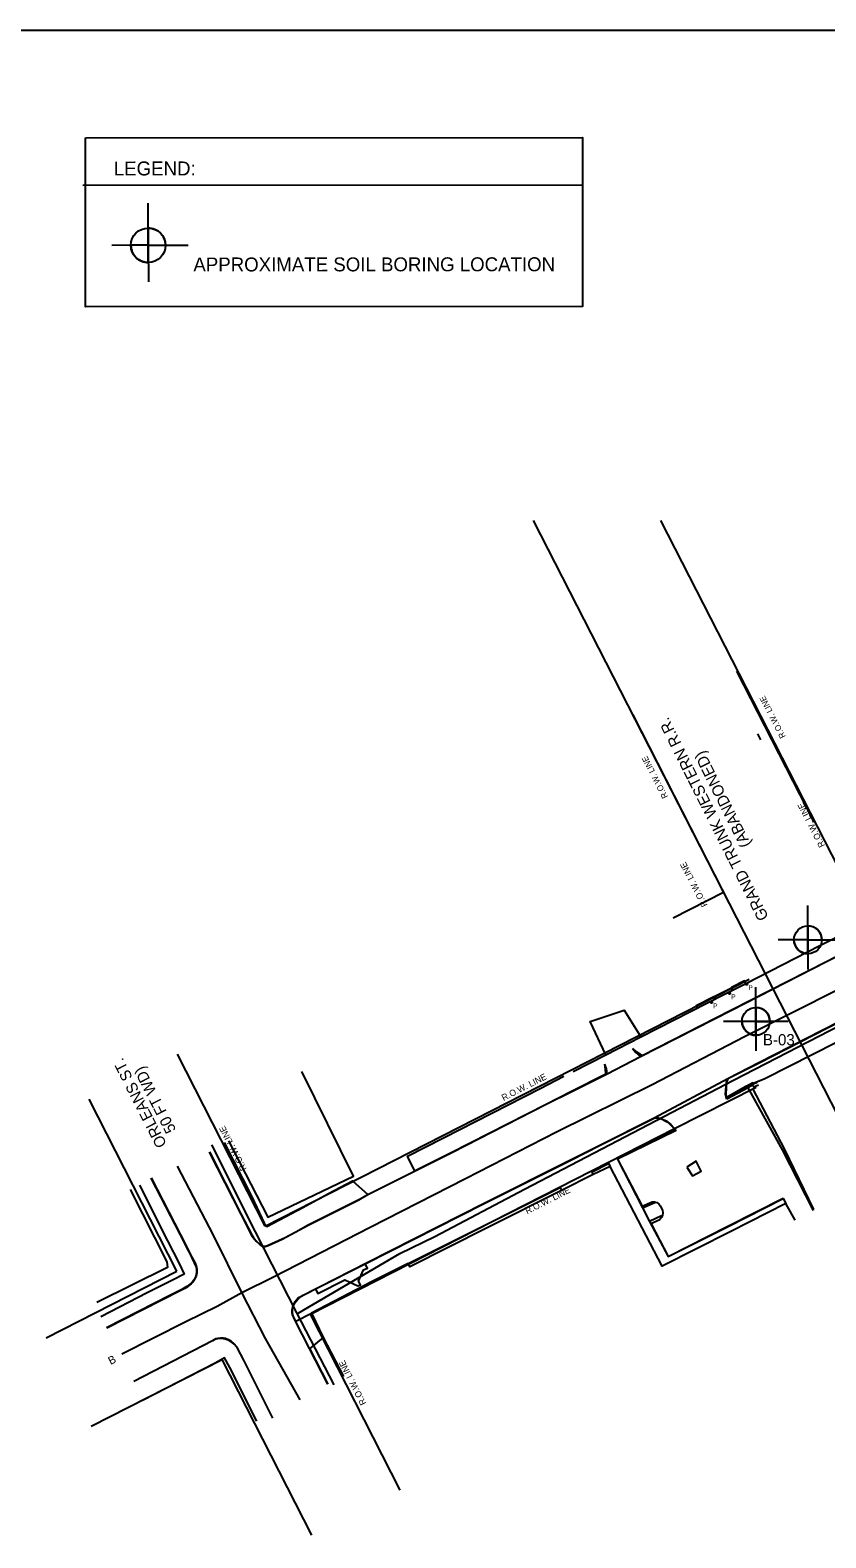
# Model space of a CAD drawing. Extents: x 19007.1 to 19038.2, y 21497.8 to 21516.9.
# Drawn here: x 19024.08 to 19030.07, y 21505.55 to 21516.9 of the extents above; entities that cross this region are included whole.
import ezdxf

# ---------------------------------------------------------------- set-up
doc = ezdxf.new("R2010")
doc.units = 0
for name, color, linetype in [('BORDER', 7, 'Continuous'), ('DETAIL_TEXT_DIMEN_PR', 7, 'Continuous'), ('G-ANNO-TTLB', 7, 'Continuous'), ('TYPICAL_TEXT_DIMEN_PR', 7, 'Continuous'), ('V-ANNO-TEXT', 7, 'Continuous'), ('V-BLDG-OTLN', 7, 'Continuous'), ('V-DEMO-PVMT', 7, 'Continuous'), ('V-PROP-RWAY', 7, 'Continuous'), ('V-PROP-RWAY-IDEN', 7, 'Continuous'), ('V-PVMT-CNTR', 7, 'Continuous'), ('V-PVMT-ROAD', 7, 'Continuous'), ('V-SITE-FEAT-DEMO', 7, 'Continuous'), ('V-SITE-FENC', 7, 'Continuous'), ('V-SITE-STRS', 7, 'Continuous'), ('V-SITE-WALK', 7, 'Continuous'), ('V-UTIL-OVHD', 7, 'Continuous')]:
    doc.layers.add(name, color=color, linetype=linetype)

msp = doc.modelspace()

# ---------------------------------------------------------------- linework, layer by layer
at = {"layer": 'G-ANNO-TTLB'}
msp.add_lwpolyline([(19036.479, 21497.785), (19007.136, 21497.785), (19007.136, 21516.9), (19036.479, 21516.9)], close=True, dxfattribs=at)
at = {"layer": 'TYPICAL_TEXT_DIMEN_PR'}
for p, q in [((19024.473, 21515.732), (19028.235, 21515.735)), ((19024.966, 21515.28), (19024.966, 21515.598)), ((19024.966, 21515.28), (19024.691, 21515.279)), ((19024.966, 21515.28), (19024.967, 21515.004)), ((19024.966, 21515.28), (19025.267, 21515.28)), ((19029.931, 21510.05), (19029.93, 21510.308)), ((19029.931, 21510.05), (19029.707, 21510.05)), ((19029.931, 21510.05), (19029.931, 21509.827)), ((19029.931, 21510.05), (19030.174, 21510.05)), ((19029.54, 21509.436), (19029.539, 21509.694)), ((19029.54, 21509.436), (19029.296, 21509.436)), ((19029.54, 21509.436), (19029.54, 21509.213)), ((19029.783, 21509.436), (19029.54, 21509.436))]:
    msp.add_line(p, q, dxfattribs=at)
msp.add_lwpolyline([(19024.493, 21516.09), (19028.234, 21516.093), (19028.235, 21514.819), (19024.494, 21514.817)], close=True, dxfattribs=at)
for points in [[(19024.966, 21515.41), (19024.966, 21515.28), (19025.096, 21515.28)], [(19024.966, 21515.15), (19024.966, 21515.28), (19024.836, 21515.28)], [(19029.93, 21510.155), (19029.931, 21510.05), (19030.036, 21510.05)], [(19029.931, 21509.945), (19029.931, 21510.05), (19029.825, 21510.05)], [(19029.539, 21509.542), (19029.54, 21509.436), (19029.645, 21509.436)], [(19029.54, 21509.331), (19029.54, 21509.436), (19029.434, 21509.436)]]:
    msp.add_lwpolyline(points, dxfattribs=at)
for centre, radius in [((19024.966, 21515.28), 0.13), ((19029.931, 21510.05), 0.105), ((19029.54, 21509.436), 0.105)]:
    msp.add_circle(centre, radius, dxfattribs=at)
for centre, radius, start, end in [((19024.966, 21515.28), 0.13, 0.0399, 90.0399), ((19024.966, 21515.28), 0.13, 180.0399, 270.0399), ((19029.931, 21510.05), 0.105, 0.0399, 90.0399), ((19029.931, 21510.05), 0.105, 180.0399, 270.0399), ((19029.54, 21509.436), 0.105, 0.0399, 90.0399), ((19029.54, 21509.436), 0.105, 180.0399, 270.0399)]:
    msp.add_arc(centre, radius, start, end, dxfattribs=at)
at = {"layer": 'V-BLDG-OTLN'}
for points in [[(19029.361, 21509.674), (19029.355, 21509.685), (19029.225, 21509.62), (19029.232, 21509.607)], [(19029.465, 21509.721), (19029.455, 21509.741), (19029.357, 21509.69), (19029.365, 21509.674)], [(19029.229, 21509.606), (19029.222, 21509.621), (19029.091, 21509.553), (19029.098, 21509.539)], [(19029.55, 21508.975), (19029.522, 21508.963), (19029.516, 21508.973), (19029.466, 21508.946), (19029.471, 21508.934), (19029.515, 21508.957), (19029.524, 21508.942), (19029.559, 21508.959)], [(19029.836, 21507.94), (19029.766, 21508.065), (19029.35, 21507.854), (19028.833, 21507.592), (19028.442, 21508.344), (19028.316, 21508.282), (19028.076, 21508.161), (19027.518, 21507.882), (19026.936, 21507.588), (19026.923, 21507.612), (19026.646, 21507.474), (19026.194, 21507.238), (19026.283, 21507.056), (19026.435, 21506.761)], [(19028.316, 21508.282), (19028.307, 21508.304), (19028.431, 21508.365), (19028.442, 21508.344)], [(19026.923, 21507.612), (19027.505, 21507.903), (19028.067, 21508.185), (19028.076, 21508.161)], [(19025.784, 21506.424), (19025.58, 21506.829), (19025.539, 21506.902), (19025.469, 21506.862), (19024.923, 21506.582)]]:
    msp.add_lwpolyline(points, dxfattribs=at)
at = {"layer": 'V-DEMO-PVMT'}
for points in [[(19028.154, 21508.908), (19028.419, 21509.041), (19028.546, 21509.107), (19028.672, 21509.171), (19029.356, 21509.521), (19030.072, 21509.886), (19030.709, 21510.21), (19030.76, 21510.239), (19031.052, 21510.392)], [(19028.164, 21509.058), (19028.409, 21509.183), (19028.674, 21509.32), (19029.298, 21509.638), (19029.465, 21509.721), (19030.021, 21510.007), (19030.58, 21510.287), (19030.524, 21510.391)], [(19028.612, 21509.233), (19028.641, 21509.206), (19028.684, 21509.18), (19029.355, 21509.523), (19030.071, 21509.887), (19030.646, 21510.185), (19030.683, 21510.202)], [(19028.361, 21508.502), (19028.774, 21508.709), (19029.328, 21509.006), (19029.561, 21509.125), (19030.285, 21509.494), (19030.794, 21509.753), (19030.943, 21509.826), (19031.258, 21509.988)], [(19029.318, 21508.865), (19029.315, 21508.887), (19029.321, 21508.977), (19029.333, 21509.007), (19029.563, 21509.123), (19030.284, 21509.492), (19030.796, 21509.751), (19030.944, 21509.823)], [(19028.61, 21509.232), (19028.635, 21509.201), (19028.672, 21509.171)], [(19028.153, 21508.91), (19028.41, 21509.04), (19028.407, 21509.077), (19028.403, 21509.113)], [(19028.419, 21509.041), (19028.414, 21509.078), (19028.403, 21509.113)], [(19029.322, 21508.85), (19029.311, 21508.887), (19029.319, 21508.976), (19029.328, 21509.006)], [(19028.362, 21508.5), (19028.774, 21508.706), (19028.781, 21508.709), (19028.794, 21508.71), (19028.807, 21508.709), (19028.834, 21508.699), (19028.869, 21508.68), (19028.884, 21508.669), (19028.908, 21508.646), (19028.919, 21508.634), (19028.925, 21508.627)], [(19028.774, 21508.709), (19028.802, 21508.708), (19028.815, 21508.706), (19028.835, 21508.7), (19028.853, 21508.692), (19028.864, 21508.686), (19028.886, 21508.67), (19028.899, 21508.659), (19028.921, 21508.635), (19028.939, 21508.613)], [(19028.925, 21508.627), (19028.935, 21508.614)]]:
    msp.add_lwpolyline(points, dxfattribs=at)
at = {"layer": 'V-PROP-RWAY'}
for p, q in [((19031.526, 21506.047), (19027.866, 21513.207)), ((19028.821, 21513.208), (19032.481, 21506.048)), ((19029.394, 21512.072), (19029.976, 21510.937)), ((19028.613, 21511.743), (19029.296, 21510.407)), ((19029.552, 21511.6), (19029.575, 21511.556)), ((19029.296, 21510.407), (19028.918, 21510.213)), ((19025.847, 21507.894), (19029.489, 21509.753)), ((19025.847, 21507.894), (19025.187, 21509.188)), ((19028.927, 21508.628), (19029.542, 21508.941)), ((19025.182, 21507.555), (19024.522, 21508.849)), ((19026.187, 21507.23), (19028.927, 21508.628)), ((19024.197, 21507.053), (19025.182, 21507.555)), ((19026.862, 21505.905), (19026.187, 21507.23)), ((19024.536, 21506.388), (19025.522, 21506.89)), ((19026.197, 21505.566), (19025.522, 21506.89))]:
    msp.add_line(p, q, dxfattribs=at)
at = {"layer": 'V-PVMT-CNTR'}
for points in [[(19024.768, 21506.931), (19025.248, 21507.176), (19025.486, 21507.292), (19025.671, 21507.393), (19025.91, 21507.513), (19026.637, 21507.887), (19027.353, 21508.253), (19028.04, 21508.603), (19028.758, 21508.961), (19029.453, 21509.321), (19030.166, 21509.682), (19030.805, 21510.009), (19031.46, 21510.342), (19032.157, 21510.701), (19032.83, 21511.045), (19033.573, 21511.424), (19034.313, 21511.797), (19035, 21512.147), (19035.429, 21512.364)], [(19026.11, 21506.586), (19025.85, 21507.047), (19025.671, 21507.393), (19025.457, 21507.825), (19025.187, 21508.346)]]:
    msp.add_lwpolyline(points, dxfattribs=at)
at = {"layer": 'V-PVMT-ROAD'}
for points in [[(19028.409, 21509.183), (19028.292, 21509.436), (19028.547, 21509.521), (19028.674, 21509.32)], [(19025.426, 21508.451), (19025.662, 21507.985), (19025.743, 21507.826), (19025.753, 21507.81), (19025.779, 21507.781), (19025.806, 21507.755), (19025.826, 21507.743), (19025.836, 21507.74), (19025.846, 21507.741), (19025.869, 21507.749), (19025.975, 21507.796), (19026.17, 21507.9), (19026.552, 21508.092), (19026.618, 21508.131), (19027.25, 21508.448), (19027.962, 21508.812), (19028.154, 21508.908)], [(19026.971, 21508.311), (19027.247, 21508.449), (19027.96, 21508.812), (19028.153, 21508.91)], [(19029.319, 21508.864), (19029.332, 21508.867), (19029.466, 21508.946)], [(19029.973, 21508.011), (19029.739, 21508.469), (19029.504, 21508.894), (19029.481, 21508.936), (19029.322, 21508.85)], [(19028.935, 21508.614), (19028.497, 21508.399), (19028.687, 21508.031), (19028.74, 21507.929), (19028.879, 21507.664), (19029.33, 21507.891), (19029.745, 21508.101), (19029.766, 21508.065)], [(19028.939, 21508.613), (19028.499, 21508.399), (19028.683, 21508.043), (19028.742, 21508.069), (19028.758, 21508.076), (19028.776, 21508.077), (19028.793, 21508.072), (19028.808, 21508.061), (19028.819, 21508.047), (19028.819, 21508.046), (19028.837, 21508.013), (19028.84, 21507.994), (19028.837, 21507.975), (19028.829, 21507.958), (19028.816, 21507.944), (19028.808, 21507.94), (19028.752, 21507.911), (19028.88, 21507.666), (19029.329, 21507.893), (19029.746, 21508.104)], [(19025.427, 21508.453), (19025.663, 21507.987), (19025.745, 21507.828), (19025.758, 21507.808), (19025.765, 21507.799), (19025.779, 21507.782), (19025.798, 21507.763), (19025.809, 21507.755), (19025.825, 21507.745), (19025.834, 21507.743), (19025.845, 21507.743), (19025.852, 21507.744), (19025.868, 21507.75), (19025.973, 21507.798), (19025.992, 21507.806), (19026.078, 21507.852), (19026.166, 21507.901), (19026.55, 21508.094)], [(19026.318, 21506.703), (19026.18, 21506.973), (19026.075, 21507.178), (19026.061, 21507.205), (19026.052, 21507.228), (19026.049, 21507.24), (19026.049, 21507.261), (19026.051, 21507.274), (19026.06, 21507.301), (19026.072, 21507.326), (19026.08, 21507.336), (19026.093, 21507.351), (19026.105, 21507.36), (19026.132, 21507.375), (19026.618, 21507.622), (19027.495, 21508.066), (19028.15, 21508.396), (19028.361, 21508.502)], [(19026.077, 21507.177), (19026.062, 21507.205), (19026.057, 21507.217), (19026.052, 21507.241), (19026.052, 21507.261), (19026.054, 21507.275), (19026.063, 21507.301), (19026.072, 21507.318), (19026.079, 21507.329), (19026.096, 21507.349), (19026.119, 21507.367), (19026.132, 21507.375), (19026.224, 21507.421), (19026.599, 21507.611), (19027.495, 21508.064), (19028.151, 21508.394), (19028.362, 21508.5)], [(19029.021, 21508.337), (19029.063, 21508.273), (19029.128, 21508.308), (19029.089, 21508.383), (19029.021, 21508.337)], [(19024.986, 21508.255), (19025.207, 21507.828), (19025.269, 21507.705), (19025.293, 21507.659), (19025.313, 21507.618), (19025.323, 21507.595), (19025.326, 21507.584), (19025.329, 21507.567), (19025.329, 21507.542), (19025.324, 21507.518), (19025.32, 21507.508), (19025.31, 21507.488), (19025.3, 21507.475), (19025.287, 21507.462), (19025.257, 21507.439), (19025.22, 21507.416), (19025.2, 21507.406), (19025.134, 21507.375), (19024.653, 21507.128)], [(19024.989, 21508.257), (19025.209, 21507.828), (19025.295, 21507.66), (19025.316, 21507.619), (19025.326, 21507.596), (19025.329, 21507.585), (19025.332, 21507.568), (19025.332, 21507.543), (19025.326, 21507.518), (19025.32, 21507.502), (19025.308, 21507.482), (19025.301, 21507.472), (19025.289, 21507.459), (19025.28, 21507.451), (19025.261, 21507.437), (19025.242, 21507.425), (19025.201, 21507.405), (19024.654, 21507.125)], [(19024.831, 21508.169), (19025.105, 21507.624), (19025.111, 21507.583), (19024.579, 21507.319)], [(19026.228, 21507.414), (19026.242, 21507.387), (19026.447, 21507.489), (19026.544, 21507.444), (19026.563, 21507.452), (19026.549, 21507.48), (19026.587, 21507.564), (19026.616, 21507.578), (19026.599, 21507.611)], [(19026.077, 21507.177), (19026.194, 21507.238)], [(19025.905, 21506.448), (19025.686, 21506.885), (19025.639, 21506.974), (19025.632, 21506.986), (19025.614, 21507.007), (19025.59, 21507.027), (19025.576, 21507.035), (19025.547, 21507.047), (19025.531, 21507.05), (19025.509, 21507.051), (19025.489, 21507.048), (19025.476, 21507.044), (19025.449, 21507.031), (19024.858, 21506.724)], [(19025.685, 21506.885), (19025.638, 21506.974), (19025.631, 21506.986), (19025.613, 21507.006), (19025.601, 21507.016), (19025.575, 21507.032), (19025.546, 21507.043), (19025.531, 21507.046), (19025.509, 21507.048), (19025.489, 21507.045), (19025.476, 21507.042), (19025.449, 21507.03), (19024.859, 21506.724)], [(19026.283, 21507.056), (19026.182, 21506.973)], [(19026.32, 21506.704), (19026.182, 21506.973)]]:
    msp.add_lwpolyline(points, dxfattribs=at)
at = {"layer": 'V-SITE-FEAT-DEMO'}
for centre, radius in [((19029.341, 21509.647), 0.00597), ((19029.341, 21509.647), 0.00299), ((19029.47, 21509.716), 0.00597), ((19029.47, 21509.716), 0.00299), ((19029.205, 21509.579), 0.00597), ((19029.205, 21509.579), 0.00299)]:
    msp.add_circle(centre, radius, dxfattribs=at)
at = {"layer": 'V-SITE-FENC'}
for points in [[(19025.571, 21508.536), (19025.867, 21507.962), (19026.512, 21508.27), (19026.121, 21509.058)], [(19029.975, 21508.02), (19029.755, 21508.476), (19029.52, 21508.926)]]:
    msp.add_lwpolyline(points, dxfattribs=at)
at = {"layer": 'V-SITE-STRS'}
for points in [[(19028.687, 21508.031), (19028.78, 21508.072)], [(19028.829, 21507.971), (19028.74, 21507.929)]]:
    msp.add_lwpolyline(points, dxfattribs=at)
at = {"layer": 'V-SITE-WALK'}
for points in [[(19029.319, 21508.864), (19029.464, 21508.948), (19029.607, 21509.006), (19030.324, 21509.37), (19030.659, 21509.543), (19030.67, 21509.524)], [(19026.971, 21508.312), (19026.917, 21508.421), (19027.189, 21508.56), (19027.916, 21508.931), (19028.095, 21509.023)], [(19025.537, 21508.524), (19025.746, 21508.115), (19025.839, 21507.915), (19025.859, 21507.89), (19025.996, 21507.963), (19026.129, 21508.033), (19026.324, 21508.14), (19026.504, 21508.235), (19026.618, 21508.131)], [(19024.9, 21508.203), (19025.112, 21507.783), (19025.2, 21507.612), (19025.237, 21507.532), (19025.149, 21507.487), (19024.959, 21507.392), (19024.609, 21507.211)]]:
    msp.add_lwpolyline(points, dxfattribs=at)
at = {"layer": 'V-UTIL-OVHD'}
for points in [[(19026.095, 21507.239), (19026.861, 21507.688), (19027.124, 21507.817), (19027.797, 21508.171), (19029.371, 21508.994), (19031.307, 21509.992), (19031.943, 21510.304), (19033.04, 21510.864)], [(19025.442, 21508.507), (19025.77, 21507.852), (19026.081, 21507.241), (19026.363, 21506.7)]]:
    msp.add_lwpolyline(points, dxfattribs=at)

# ---------------------------------------------------------------- texts
msp.add_text('B', height=0.0597, rotation=27.0313).set_placement((19024.683, 21506.848))
at = {"layer": 'BORDER'}
for s, height, p in [('LEGEND:', 0.105, (19024.707, 21515.806)), ('APPROXIMATE SOIL BORING LOCATION', 0.10498, (19025.306, 21515.083))]:
    msp.add_text(s, height=height, rotation=0.0399, dxfattribs=at).set_placement(p)
at = {"layer": 'DETAIL_TEXT_DIMEN_PR'}
msp.add_text('B-03', height=0.085, rotation=0.0399, dxfattribs=at).set_placement((19029.592, 21509.255))
at = {"layer": 'V-ANNO-TEXT'}
for s, height, rotation, p in [('GRAND TRUNK WESTERN R.R.', 0.08503, 116.6596, (19029.638, 21510.22)), ('(ABANDONED)', 0.08503, 116.6596, (19029.505, 21510.77)), ('ORLEANS ST. ', 0.08361, 117.0313, (19025.108, 21508.51)), ('50 FT WD)', 0.0836, 117.0313, (19025.178, 21508.619))]:
    msp.add_text(s, height=height, rotation=rotation, dxfattribs=at).set_placement(p)
at = {"layer": 'V-PROP-RWAY-IDEN'}
for height, rotation, p in [(0.04535, 117.1686, (19029.765, 21511.581)), (0.04535, 117.1686, (19028.879, 21511.128)), (0.04778, 117.0313, (19030.061, 21510.76)), (0.04778, 117.0313, (19029.177, 21510.312)), (0.04778, 27.0313, (19027.641, 21508.836)), (0.04778, 117.0313, (19025.708, 21508.325)), (0.04778, 27.0313, (19027.819, 21507.982)), (0.04778, 117.0313, (19026.609, 21506.56))]:
    msp.add_text('R.O.W. LINE', height=height, rotation=rotation, dxfattribs=at).set_placement(p)
at = {"layer": 'V-SITE-FEAT-DEMO'}
for p in [(19029.483, 21509.672), (19029.218, 21509.535), (19029.354, 21509.603)]:
    msp.add_text('P', height=0.0358, rotation=360, dxfattribs=at).set_placement(p)

doc.saveas('drawing.dxf')
